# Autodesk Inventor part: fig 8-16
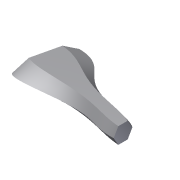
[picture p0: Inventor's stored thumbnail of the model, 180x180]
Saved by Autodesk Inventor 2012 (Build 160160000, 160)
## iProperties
Created: 2004-05
Part Number: fig 8-16
Document SubType Name: Modeling
Designer: CADCIM Technologies
Manufacturer: Standard
Standards Organization: Custom
Density: 1 g/cm^3
Material: Default
Author: CADCIM Technologies
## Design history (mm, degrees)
workplane "Work Plane2"
sketch "Sketch7"
  geometry: L1 (-42.583, 6.068)-(-42.583, 0.37) reference; 5 further points
  constraints: 1 point on line, 5 other
sketch "Sketch8"
  geometry: L1 (-42.583, 3.219)-(-107.269, 18.236); L2 (-42.583, 6.068)-(-42.583, 0.37) reference
  constraints: 2 end point, 1 midpoint
sweep "Sweep7" sketch "Sketch7", "Sketch8" dims "d6" = 0
body "Solid1"
sketch "Sketch2"
  geometry: L1 (-5.697, 0)-(-2.849, 4.934); L2 (-2.849, 4.934)-(2.849, 4.934); L3 (2.849, 4.934)-(5.697, 0); L4 (5.697, 0)-(2.849, -4.934); L5 (2.849, -4.934)-(-2.849, -4.934); L6 (-2.849, -4.934)-(-5.697, 0); 2 further points
  constraints: 12 end point, 1 coincident, 12 other
